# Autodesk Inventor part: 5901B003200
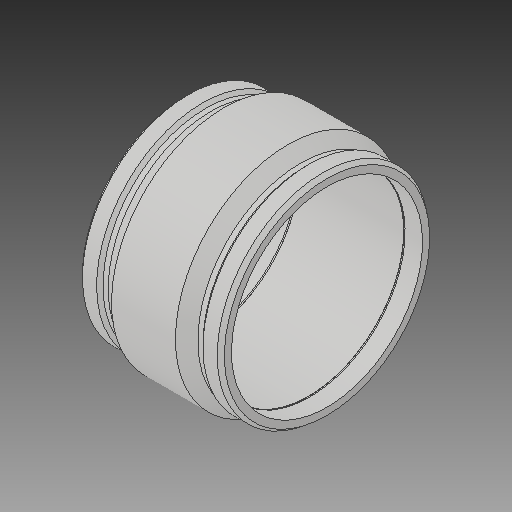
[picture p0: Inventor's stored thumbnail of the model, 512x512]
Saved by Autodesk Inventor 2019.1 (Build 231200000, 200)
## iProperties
Created: 2017-06
Part Number: 5901B003200
Material: Generic
Description: PLASSON IPS COUPLER 20''
Document SubType Name: Modeling
Designer: KIM
Mass: 8622.19 g
Surface Area: 6772.47 cm^2
Volume: 8622.19 cm^3
Density: 1 g/cm^3
Appearance: Default
Author: KIM
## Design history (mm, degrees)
derived "5901B.ipt"
feature "Solid1::5901B.ipt"
tag "TaggingFeature1"
body "Solid1"
other parameters: "d0" = 375.92, "d1" = 505.7, "d2" = 595.884, "d3" = 187.96, "d4" = 93.98, "d5" = 536.2956, "d6" = 404.56, "d7" = 505.7, "d8" = 168 deg, "d10" = 75.184, "d11" = 25.06133, "d13" = 375.92, "d14" = 17.6296, "d18" = 505.7, "d19" = 3.52592, "d20" = 168 deg, "d22" = 560.13096, "d23" = 595.884, "d24" = 543.32703, "d25" = 135 deg, "d26" = 169.164, "d27" = 135 deg, "d29" = 281.94, "d30" = 15, "d31" = 131.572, "d34" = 5 deg, "d35" = 15, "d39" = 5 deg, "d41" = 4, "d42" = 14, "d43" = 0, "d45" = 4, "d46" = 14, "d47" = 0, "d48" = 3, "d49" = 0, "d50" = 3, "d51" = 0, "d52" = 54.5084, "d53" = 13.6271, "d55" = 187.96, "d_" = 505.7, "L_" = 375.92, "L_1" = 187.96, "D_" = 595.884, "A_" = 281.94, "d_2" = 12, "B_" = 281.94
